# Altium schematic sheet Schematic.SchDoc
size A4
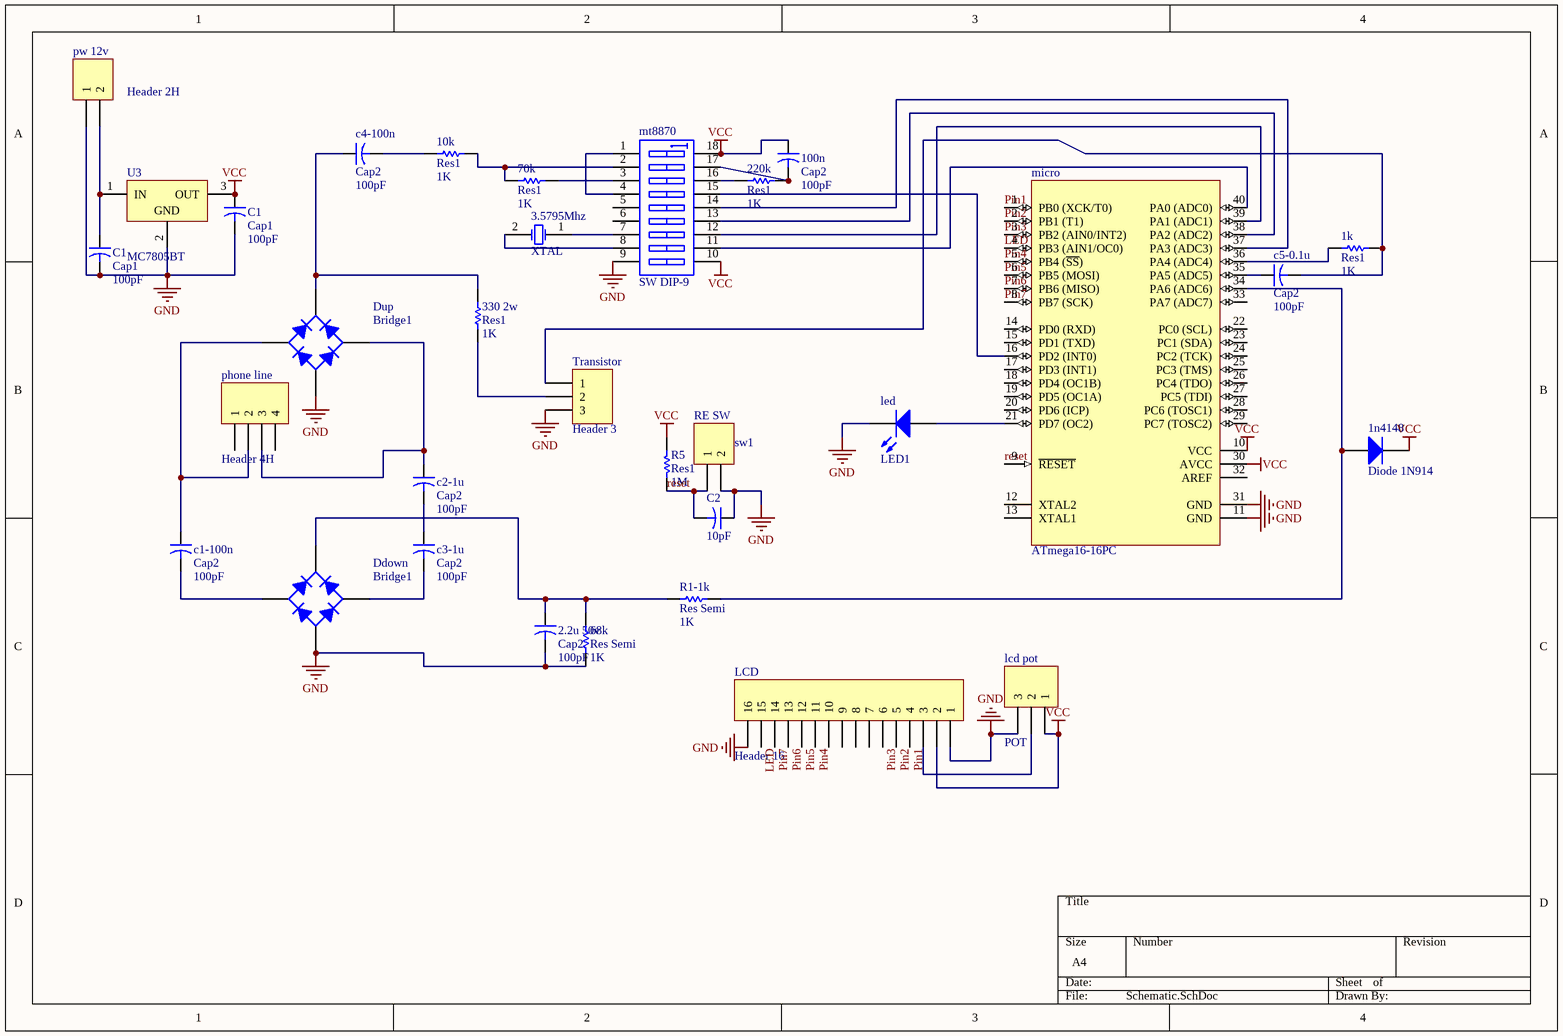
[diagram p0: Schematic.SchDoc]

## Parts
(Parts that share a designator on the sheet are numbered #1, #2 ... from top to bottom, then left to right.)
1k  Res1  value 1K  [AXIAL-0.3]
1n4148  Diode 1N914  [DO-35]
2.2u_50v  Cap2  value 100pF  [CAPR5-4X5]
3.5795Mhz  XTAL  [R38]
10k  Res1  value 1K  [AXIAL-0.3]
68k  Res Semi  value 1K  [AXIAL-0.5]
70k  Res1  value 1K  [AXIAL-0.3]
100n  Cap2  value 100pF  [CAPR5-4X5]
220k  Res1  value 1K  [AXIAL-0.3]
330_2w  Res1  value 1K  [AXIAL-0.3]
C1#1  Cap1  value 100pF  [CAPR5-4X5]
C1#2  Cap1  value 100pF  [CAPR5-4X5]
c1-100n  Cap2  value 100pF  [CAPR5-4X5]
C2  value 10pF  [CAP1]
c2-1u  Cap2  value 100pF  [CAPR5-4X5]
c3-1u  Cap2  value 100pF  [CAPR5-4X5]
c4-100n  Cap2  value 100pF  [CAPR5-4X5]
c5-0.1u  Cap2  value 100pF  [CAPR5-4X5]
Ddown  Bridge1  [D-38]
Dup  Bridge1  [D-38]
LCD  Header 16  [lcd2*16]
lcd_pot  POT  [pot1]
led  LED1  [LED-1]
micro  ATmega16-16PC  [40P6]
mt8870  SW DIP-9  [DIP-18]
phone_line  Header 4H  [JACK LINE]
pw_12v  Header 2H  [HDR1X2H]
R1-1k  Res Semi  value 1K  [AXIAL-0.5]
R5  Res1  value 1M  [AXIAL-0.3]
RE_SW  sw1  [MICROSWITCH4]
Transistor  Header 3  [HDR1X3]
U3  MC7805BT  [REG2]

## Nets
GND: 2.2u_50v.2 68k.1 C1#1.2 C1#2.2 C2.1 Ddown.3(A) Dup.3(A) LCD.1 LCD.16 lcd_pot.3 led.2(K) micro.11(GND) micro.31(GND) mt8870.9(A9) pw_12v.1 RE_SW.2 Transistor.3 U3.2(GND)
VCC: 1n4148.2(K) 100n.1 C1#1.1 LCD.2 lcd_pot.1 micro.10(VCC) micro.30(AVCC) mt8870.10(B9) mt8870.18(B1) R5.2 U3.3(OUT)
LED: LCD.15 micro.4(PB3_(AIN1/OC0))
Pin1: LCD.4 micro.1(PB0_(XCK/T0))
Pin2: LCD.5 micro.2(PB1_(T1))
Pin3: LCD.6 micro.3(PB2_(AIN0/INT2))
Pin4: LCD.11 micro.5(PB4_(~{SS}))
Pin5: LCD.12 micro.6(PB5_(MOSI))
Pin6: LCD.13 micro.7(PB6_(MISO))
Pin7: LCD.14 micro.8(PB7_(SCK))
reset: C2.2 micro.9(~{RESET}) R5.1 RE_SW.1
Net1k_1: 1k.1 c5-0.1u.2 Transistor.1
Net1k_2: 1k.2 micro.36(PA4_(ADC4))
Net1n4148_1: 1n4148.1(A) micro.34(PA6_(ADC6)) R1-1k.2
Net2.2u_50v_1: 2.2u_50v.1 68k.2 Ddown.1(K) R1-1k.1
Net3.5795Mhz_1: 3.5795Mhz.1(OSC1) mt8870.7(A7)
Net3.5795Mhz_2: 3.5795Mhz.2(OSC2) mt8870.8(A8)
Net10k_1: 10k.1 c4-100n.2
Net10k_2: 10k.2 70k.1 mt8870.2(A2)
Net70k_2: 70k.2 mt8870.3(A3)
Net100n_2: 100n.2 220k.1 mt8870.17(B2)
Net220k_2: 220k.2 mt8870.16(B3)
Net330_2w_1: 330_2w.1 Transistor.2
Net330_2w_2: 330_2w.2 c4-100n.1 Dup.1(K)
NetC1#2_1: C1#2.1 pw_12v.2 U3.1(IN)
Netc1-100n_1: c1-100n.1 Dup.4(C) phone_line.2
Netc1-100n_2: c1-100n.2 Ddown.4(C)
Netc2-1u_1: c2-1u.1 Dup.2(C) phone_line.3
Netc2-1u_2: c2-1u.2 c3-1u.1
Netc3-1u_2: c3-1u.2 Ddown.2(C)
Netc5-0.1u_1: c5-0.1u.1 micro.35(PA5_(ADC5))
NetLCD_3: LCD.3 lcd_pot.2
Netled_1: led.1(A) micro.21(PD7_(OC2))
Netmicro_16: micro.16(PD2_(INT0)) mt8870.15(B4)
Netmicro_37: micro.37(PA3_(ADC3)) mt8870.14(B5)
Netmicro_38: micro.38(PA2_(ADC2)) mt8870.13(B6)
Netmicro_39: micro.39(PA1_(ADC1)) mt8870.12(B7)
Netmicro_40: micro.40(PA0_(ADC0)) mt8870.11(B8)
Netmt8870_1: mt8870.1(A1) mt8870.4(A4)

Not connected (* = marked no-connect by the designer): LCD 7 8 9 10; micro 12(XTAL2) 13(XTAL1) 14(PD0_(RXD)) 15(PD1_(TXD)) 17(PD3_(INT1)) 18(PD4_(OC1B)) 19(PD5_(OC1A)) 20(PD6_(ICP)) 22(PC0_(SCL)) 23(PC1_(SDA)) 24(PC2_(TCK)) 25(PC3_(TMS)) 26(PC4_(TDO)) 27(PC5_(TDI)) 28(PC6_(TOSC1)) 29(PC7_(TOSC2)) 32(AREF) 33(PA7_(ADC7)); mt8870 5(A5) 6(A6); phone_line 1 4

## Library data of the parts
1k 10k 70k 220k 330_2w R5 = Res1: Resistor
1n4148 = Diode 1N914: High Conductance Fast Diode
2.2u_50v 100n C1#1 C1#2 c1-100n C2 c2-1u c3-1u c4-100n c5-0.1u = Cap2: Capacitor
3.5795Mhz = XTAL: Crystal Oscillator
68k R1-1k = Res Semi: Semiconductor Resistor
Ddown Dup = Bridge1: Full Wave Diode Bridge
LCD = Header 16: Header, 16-Pin
lcd_pot = Header 3: Header, 3-Pin; pin to pad: 2>3 3>2
led = LED1: Typical RED GaAs LED
micro = ATmega16-16PC: 8-Bit AVR Microcontroller with 16K Bytes of In-System Programmable Flash Memory
mt8870 = SW DIP-9: DIP Switch, 9 Position, SPST
phone_line = Header 4H: Header, 4-Pin, Right Angle
pw_12v = Header 2H: Header, 2-Pin, Right Angle
RE_SW = Header 2: Header, 2-Pin
Transistor = Header 3: Header, 3-Pin
U3 = MC7805BT: 3-Terminal Positive Fixed Voltage Regulator; Note: Pin 2 is electrically connected to TAB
